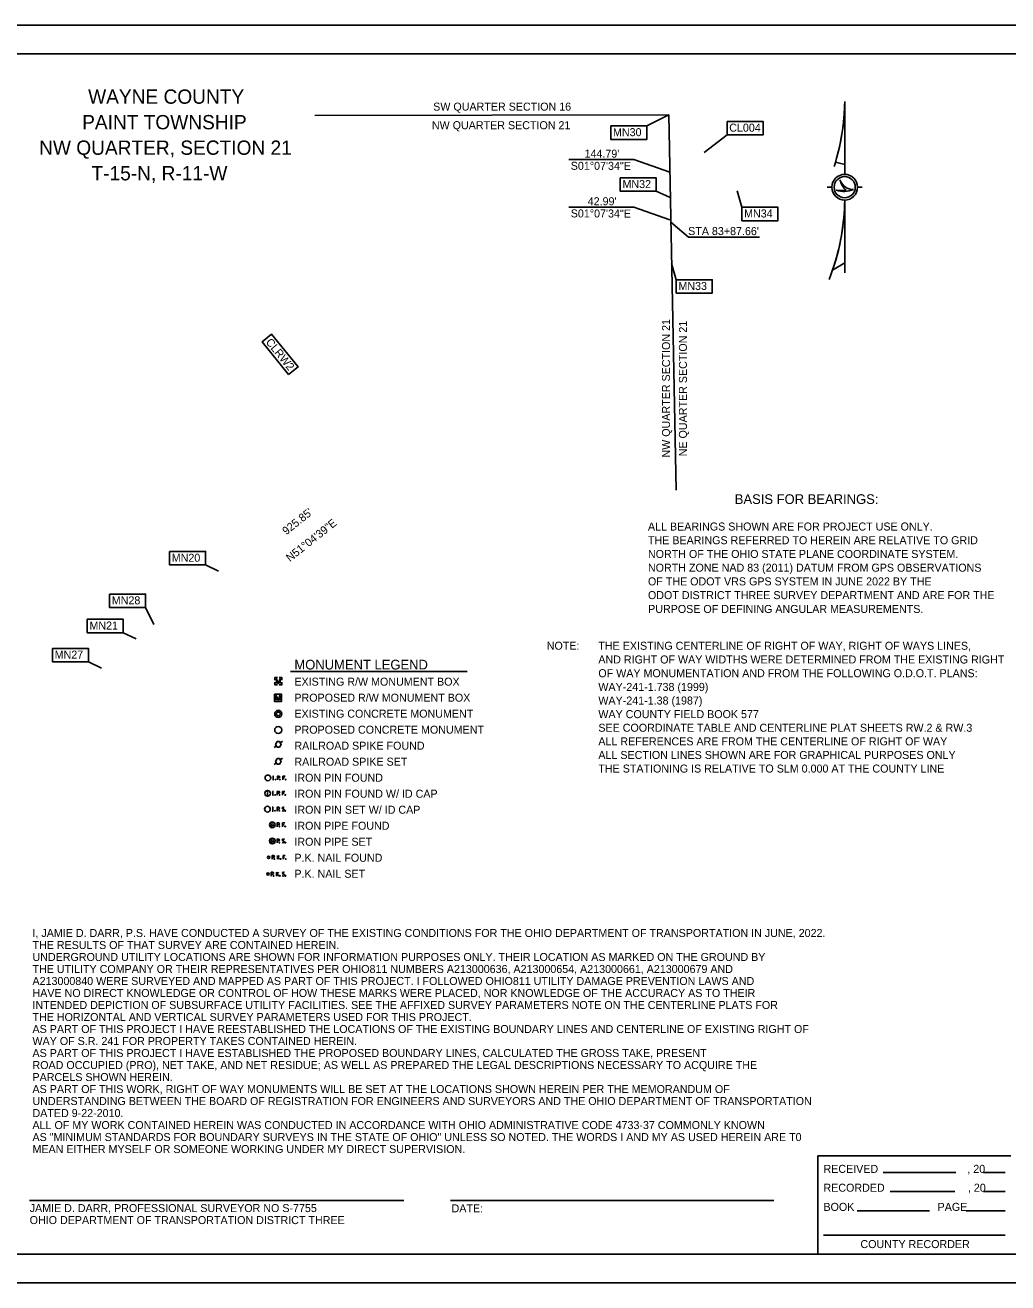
# Model space of a CAD drawing. Extents: x 2183298 to 2188248, y 369076 to 371276.
# Drawn here: x 2184773 to 2186493, y 369076 to 371276 of the extents above; entities that cross this region are included whole.
import ezdxf

# ---------------------------------------------------------------- set-up
doc = ezdxf.new("R2010")
doc.units = 0
for name, color, linetype in [('_CIVIL_CONSTRUCTION', 7, 'Continuous'), ('Default', 7, 'Continuous'), ('RD_X_RR_Cells', 7, 'Continuous'), ('SC_Scratch1', 7, 'Continuous'), ('SV_P_Mon_Cells_Set', 7, 'Continuous'), ('SV_X_Mon_Cells_Found', 7, 'Continuous'), ('SV_X_Shot_Marker', 7, 'Continuous')]:
    doc.layers.add(name, color=color, linetype=linetype)

msp = doc.modelspace()

# ---------------------------------------------------------------- linework, layer by layer
at = {"layer": 'RD_X_RR_Cells'}
msp.add_lwpolyline([(2183447.7, 371226.3), (2186647.7, 371226.3), (2186647.7, 369126.3), (2183447.7, 369126.3)], close=True, dxfattribs=at)
at = {"layer": 'SC_Scratch1'}
for q in [(2185280, 371118.1), (2185912.2, 370462.7)]:
    msp.add_line((2185899.3, 371119.5), q, dxfattribs=at)
at = {"layer": 'SV_P_Mon_Cells_Set'}
for p, q in [((2186207.2, 371015.3), (2186207.2, 371142.8)), ((2186191.3, 371036.9), (2186207.2, 371032.5)), ((2186176.7, 370992.8), (2186184.7, 370992.8)), ((2186229.7, 370992.8), (2186237.7, 370992.8)), ((2186207.2, 370842.8), (2186207.2, 370970.3)), ((2186207.2, 370860.3), (2186185.8, 370847.5))]:
    msp.add_line(p, q, dxfattribs=at)
for points in [[(2186191.2, 371036.9), (2186191.3, 371036.9), (2186207.2, 371032.5), (2186207.2, 371142.8)], [(2186185.8, 370847.5), (2186207.2, 370860.3), (2186207.2, 370970.3)]]:
    msp.add_lwpolyline(points, dxfattribs=at)
for radius in [22.5, 18.5]:
    msp.add_circle((2186207.2, 370992.8), radius, dxfattribs=at)
for centre, radius, start, end in [((2185813, 371148.4), 394.3, 342.4153, 359.1947), ((2185813, 371148.4), 394.3, 343.5754, 359.1947), ((2186206.1, 371030.7), 45.2, 252.4874, 291.486), ((2186201.7, 371044), 57.1, 260.7277, 277.8734), ((2186223, 371014.1), 25.5, 199.1575, 269.3709), ((2186233.8, 371013.7), 35.8, 192.8556, 227.3141), ((2185813, 370975.9), 394.3, 338.5054, 359.1947), ((2185813, 370975.9), 394.3, 340.9936, 359.1947)]:
    msp.add_arc(centre, radius, start, end, dxfattribs=at)
at = {"layer": 'SV_X_Mon_Cells_Found'}
msp.add_lwpolyline([(2183297.7, 369076.3), (2186697.7, 369076.3), (2186697.7, 371276.3), (2183297.7, 371276.3)], close=True, dxfattribs=at)
at = {"layer": 'SV_X_Shot_Marker'}
for p, q in [((2185860.9, 371100), (2185899.3, 371119.5)), ((2186001.3, 371084.4), (2185961, 371053.3)), ((2185837.9, 371041.2), (2185724.4, 371041.2)), ((2185837.9, 371041.2), (2185901.3, 371018.9)), ((2186027.3, 370957.7), (2186019.2, 370986.3)), ((2185877.5, 370985.8), (2185902, 370974.7)), ((2185837.9, 370957.9), (2185724.4, 370957.9)), ((2185837.9, 370957.9), (2185901.3, 370935.7)), ((2185934, 370905.2), (2185903, 370931.8)), ((2186058.3, 370905.2), (2185934, 370905.2)), ((2185912.4, 370830.9), (2185904.3, 370859.5)), ((2185088.8, 370332.1), (2185111.3, 370321.2)), ((2184983.9, 370257.6), (2184998.1, 370227.7)), ((2184944.8, 370213.6), (2184967.3, 370202.6)), ((2184883.8, 370162.6), (2184906.4, 370151.7)), ((2185216, 370128.8), (2185216, 370128.8)), ((2185237.2, 370145.4), (2185546.5, 370145.4)), ((2185215.6, 370099.7), (2185215.6, 370099.7)), ((2185223.4, 370023.6), (2185219.4, 370020.6)), ((2185212.7, 370015.6), (2185208.7, 370012.6)), ((2185212.7, 369985.9), (2185208.7, 369982.9)), ((2185223.4, 369993.9), (2185219.4, 369990.9)), ((2185206.2, 369962.8), (2185207.9, 369962.8)), ((2185206.2, 369962.8), (2185207.9, 369962.8)), ((2185206.2, 369956.2), (2185207.9, 369956.2)), ((2185207, 369956.2), (2185207, 369962.8)), ((2185214.7, 369959.7), (2185217.4, 369959.7)), ((2185224.1, 369956.2), (2185224.1, 369962.8)), ((2185224.1, 369962.8), (2185227.9, 369962.8)), ((2185224.1, 369959.6), (2185226.8, 369959.6)), ((2185197.4, 369933.1), (2185197.4, 369929.4)), ((2185205.8, 369935.9), (2185207.4, 369935.9)), ((2185205.8, 369935.9), (2185207.4, 369935.9)), ((2185206.6, 369929.3), (2185206.6, 369935.9)), ((2185214.3, 369932.7), (2185216.9, 369932.7)), ((2185223.6, 369929.3), (2185223.6, 369935.9)), ((2185223.6, 369935.9), (2185227.5, 369935.9)), ((2185223.6, 369932.7), (2185226.4, 369932.7)), ((2185205.3, 369908.3), (2185207, 369908.3)), ((2185205.3, 369908.3), (2185207, 369908.3)), ((2185205.8, 369929.3), (2185207.4, 369929.3)), ((2185206.2, 369901.6), (2185206.2, 369908.3)), ((2185205.3, 369901.6), (2185207, 369901.6)), ((2185213.8, 369905.1), (2185216.5, 369905.1)), ((2185223.3, 369905.9), (2185226.3, 369904.3)), ((2185214, 369877.5), (2185216.6, 369877.5)), ((2185223.3, 369874), (2185223.3, 369880.7)), ((2185223.3, 369880.7), (2185227.2, 369880.7)), ((2185223.3, 369877.5), (2185226.1, 369877.5)), ((2185214, 369849.4), (2185216.6, 369849.4)), ((2185223.4, 369850.2), (2185226.5, 369848.6)), ((2185205.1, 369820.7), (2185207.8, 369820.7)), ((2185214.5, 369817.2), (2185214.5, 369823.8)), ((2185214.5, 369819.6), (2185217.7, 369823.8)), ((2185215.5, 369821), (2185218.3, 369817.2)), ((2185224.3, 369817.2), (2185224.3, 369823.8)), ((2185224.3, 369823.8), (2185228.2, 369823.8)), ((2185224.3, 369820.6), (2185227.1, 369820.6)), ((2185203.7, 369791.4), (2185206.4, 369791.4)), ((2185213, 369787.9), (2185213, 369794.6)), ((2185213, 369790.3), (2185216.2, 369794.6)), ((2185214, 369791.7), (2185216.8, 369787.9)), ((2185223.6, 369792.2), (2185226.6, 369790.6)), ((2186160, 369126.3), (2186160, 369298.7)), ((2186160, 369298.7), (2186497.7, 369298.7)), ((2186274.3, 369269.2), (2186401.6, 369269.2)), ((2186449.9, 369269.2), (2186487.7, 369269.2)), ((2186286.8, 369235.9), (2186399.9, 369235.9)), ((2186449.9, 369235.9), (2186487.7, 369235.9)), ((2184780.5, 369220.5), (2185435.7, 369220.5)), ((2185517.5, 369220.5), (2186083.4, 369220.5)), ((2186229, 369202.5), (2186355.6, 369202.5)), ((2186419.6, 369202.5), (2186487.7, 369202.5)), ((2186170, 369159.7), (2186487.7, 369159.7))]:
    msp.add_line(p, q, dxfattribs=at)
for points in [[(2185797.9, 371100), (2185860.9, 371100), (2185860.9, 371076.5), (2185797.9, 371076.5)], [(2186001.3, 371107.8), (2186064.3, 371107.8), (2186064.3, 371084.4), (2186001.3, 371084.4)], [(2185814.5, 371009.2), (2185877.5, 371009.2), (2185877.5, 370985.8), (2185814.5, 370985.8)], [(2186027.3, 370957.7), (2186090.3, 370957.7), (2186090.3, 370934.3), (2186027.3, 370934.3)], [(2185912.4, 370830.9), (2185975.4, 370830.9), (2185975.4, 370807.5), (2185912.4, 370807.5)], [(2185234.1, 370665.3), (2185250.6, 370678.6), (2185204.4, 370735.7), (2185187.9, 370722.4)], [(2185025.8, 370355.6), (2185088.8, 370355.6), (2185088.8, 370332.1), (2185025.8, 370332.1)], [(2184920.9, 370281.1), (2184983.9, 370281.1), (2184983.9, 370257.6), (2184920.9, 370257.6)], [(2184881.8, 370237), (2184944.8, 370237), (2184944.8, 370213.6), (2184881.8, 370213.6)], [(2184820.8, 370186), (2184883.8, 370186), (2184883.8, 370162.6), (2184820.8, 370162.6)], [(2185214.2, 370023.1), (2185217.9, 370023.1), (2185220.9, 370018.1), (2185217.9, 370013.1), (2185214.2, 370013.1), (2185211.2, 370018.1)], [(2185214.2, 369993.4), (2185217.9, 369993.4), (2185220.9, 369988.4), (2185217.9, 369983.4), (2185214.2, 369983.4), (2185211.2, 369988.4)]]:
    msp.add_lwpolyline(points, close=True, dxfattribs=at)
for points in [[(2185209.8, 370130.4), (2185209.8, 370135.1), (2185214.5, 370135.1)], [(2185213, 370124.6), (2185213, 370133), (2185216, 370124.6), (2185219.1, 370133), (2185219.1, 370124.6)], [(2185217.5, 370135.1), (2185222.3, 370135.1), (2185222.3, 370130.4)], [(2185209.3, 370106), (2185221.8, 370106), (2185221.8, 370093.5), (2185209.3, 370093.5), (2185209.3, 370106)], [(2185214.5, 370122.5), (2185209.8, 370122.5), (2185209.8, 370127.2)], [(2185222.3, 370127.2), (2185222.3, 370122.5), (2185217.5, 370122.5)], [(2185212.5, 370095.6), (2185212.5, 370103.9), (2185215.6, 370095.6), (2185218.7, 370103.9), (2185218.7, 370095.6)], [(2185217.4, 369962.8), (2185214.7, 369962.8), (2185214.7, 369956.2)], [(2185216.9, 369935.9), (2185214.3, 369935.9), (2185214.3, 369929.3)], [(2185216.5, 369908.3), (2185213.8, 369908.3), (2185213.8, 369901.6)], [(2185216.6, 369880.7), (2185214, 369880.7), (2185214, 369874)], [(2185216.6, 369852.6), (2185214, 369852.6), (2185214, 369845.9)], [(2185207.8, 369823.8), (2185205.1, 369823.8), (2185205.1, 369817.2)], [(2185206.4, 369794.6), (2185203.7, 369794.6), (2185203.7, 369787.9)]]:
    msp.add_lwpolyline(points, dxfattribs=at)
for centre, radius in [((2185216, 370071.5), 6.25), ((2185216, 370071.5), 3.33), ((2185216, 370043.4), 6.25), ((2185197.9, 369959.5), 5), ((2185211, 369956.6), 0.583), ((2185218.7, 369956.6), 0.583), ((2185228.9, 369956.6), 0.583), ((2185197.4, 369932.6), 5), ((2185197.4, 369935.3), 0.667), ((2185210.6, 369929.7), 0.583), ((2185218.3, 369929.7), 0.583), ((2185228.4, 369929.7), 0.583), ((2185197, 369904.9), 5), ((2185210.2, 369902.1), 0.583), ((2185217.9, 369902.1), 0.583), ((2185228.5, 369902), 0.583), ((2185205.6, 369877.4), 5), ((2185205.6, 369877.4), 2.06), ((2185218, 369874.5), 0.583), ((2185228.1, 369874.5), 0.583), ((2185205.6, 369849.2), 5), ((2185205.6, 369849.2), 2.08), ((2185218, 369846.3), 0.583), ((2185228.7, 369846.3), 0.583), ((2185199.2, 369820.5), 2.07), ((2185209.2, 369817.6), 0.583), ((2185220.1, 369817.6), 0.583), ((2185229.1, 369817.6), 0.583), ((2185197.9, 369791.2), 2.06), ((2185207.7, 369788.3), 0.583), ((2185218.8, 369788.3), 0.583), ((2185228.8, 369788.3), 0.583)]:
    msp.add_circle(centre, radius, dxfattribs=at)
for centre, radius, start, end in [((2185217.1, 369961.2), 1.62, 278.8803, 81.1197), ((2185216.7, 369934.3), 1.62, 278.8803, 81.1197), ((2185216.3, 369906.7), 1.62, 278.8803, 81.1197), ((2185224.9, 369904.8), 3.49, 61.3463, 118.6537), ((2185223.9, 369906.9), 1.18, 126.2587, 236.3675), ((2185224.8, 369904.4), 2.76, 223.6695, 304.3963), ((2185225.3, 369903.2), 1.48, 311.4883, 47.9358), ((2185216.4, 369879.1), 1.62, 278.8803, 81.1197), ((2185216.4, 369851), 1.62, 278.8803, 81.1197), ((2185224, 369851.2), 1.18, 126.2587, 236.3675), ((2185224.9, 369848.7), 2.76, 223.6695, 304.3963), ((2185225, 369849.1), 3.49, 61.3463, 118.6537), ((2185225.5, 369847.5), 1.48, 311.4883, 47.9358), ((2185207.6, 369822.2), 1.62, 278.8803, 81.1197), ((2185206.1, 369793), 1.62, 278.8803, 81.1197), ((2185224.2, 369793.2), 1.18, 126.2587, 236.3675), ((2185225.1, 369790.7), 2.76, 223.6695, 304.3963), ((2185225.2, 369791.1), 3.49, 61.3463, 118.6537), ((2185225.6, 369789.5), 1.48, 311.4883, 47.9358)]:
    msp.add_arc(centre, radius, start, end, dxfattribs=at)

# ---------------------------------------------------------------- texts
at = {"layer": '_CIVIL_CONSTRUCTION'}
for s, rotation, p in [("144.79'", 359.8857, (2185751.9, 371044.6)), ('S01°07\'34"E', 359.8857, (2185727.8, 371023.3)), ("42.99'", 359.8857, (2185757.5, 370961.3)), ('S01°07\'34"E', 359.8857, (2185727.8, 370940)), ("STA 83+87.66'", 359.8857, (2185933.2, 370909.2)), ("925.85'", 38.4323, (2185229.9, 370383.9)), ('N51°04\'39"E', 38.4323, (2185236.4, 370336.9))]:
    msp.add_text(s, height=14, rotation=rotation, dxfattribs=at).set_placement(p)
at = {"layer": 'Default'}
for s, p in [('I, JAMIE D. DARR, P.S. HAVE CONDUCTED A SURVEY OF THE EXISTING CONDITIONS FOR THE OHIO DEPARTMENT OF TRANSPORTATION IN JUNE, 2022.', (2184785.9, 369681.3)), ('THE RESULTS OF THAT SURVEY ARE CONTAINED HEREIN.', (2184785.9, 369660.3)), ('UNDERGROUND UTILITY LOCATIONS ARE SHOWN FOR INFORMATION PURPOSES ONLY. THEIR LOCATION AS MARKED ON THE GROUND BY', (2184785.9, 369639.3)), ('THE UTILITY COMPANY OR THEIR REPRESENTATIVES PER OHIO811 NUMBERS A213000636, A213000654, A213000661, A213000679 AND', (2184785.9, 369618.3)), ('A213000840 WERE SURVEYED AND MAPPED AS PART OF THIS PROJECT. I FOLLOWED OHIO811 UTILITY DAMAGE PREVENTION LAWS AND', (2184785.9, 369597.3)), ('HAVE NO DIRECT KNOWLEDGE OR CONTROL OF HOW THESE MARKS WERE PLACED, NOR KNOWLEDGE OF THE ACCURACY AS TO THEIR', (2184785.9, 369576.3)), ('INTENDED DEPICTION OF SUBSURFACE UTILITY FACILITIES. SEE THE AFFIXED SURVEY PARAMETERS NOTE ON THE CENTERLINE PLATS FOR', (2184785.9, 369555.3)), ('THE HORIZONTAL AND VERTICAL SURVEY PARAMETERS USED FOR THIS PROJECT.', (2184785.9, 369534.3)), ('AS PART OF THIS PROJECT I HAVE REESTABLISHED THE LOCATIONS OF THE EXISTING BOUNDARY LINES AND CENTERLINE OF EXISTING RIGHT OF', (2184785.9, 369513.3)), ('WAY OF S.R. 241 FOR PROPERTY TAKES CONTAINED HEREIN.', (2184785.9, 369492.3)), ('AS PART OF THIS PROJECT I HAVE ESTABLISHED THE PROPOSED BOUNDARY LINES, CALCULATED THE GROSS TAKE, PRESENT', (2184785.9, 369471.3)), ('ROAD OCCUPIED (PRO), NET TAKE, AND NET RESIDUE; AS WELL AS PREPARED THE LEGAL DESCRIPTIONS NECESSARY TO ACQUIRE THE', (2184785.9, 369450.3)), ('PARCELS SHOWN HEREIN.', (2184785.9, 369429.3)), ('AS PART OF THIS WORK, RIGHT OF WAY MONUMENTS WILL BE SET AT THE LOCATIONS SHOWN HEREIN PER THE MEMORANDUM OF', (2184785.9, 369408.3)), ('UNDERSTANDING BETWEEN THE BOARD OF REGISTRATION FOR ENGINEERS AND SURVEYORS AND THE OHIO DEPARTMENT OF TRANSPORTATION', (2184785.9, 369387.3)), ('DATED 9-22-2010.', (2184785.9, 369366.3)), ('ALL OF MY WORK CONTAINED HEREIN WAS CONDUCTED IN ACCORDANCE WITH OHIO ADMINISTRATIVE CODE 4733-37 COMMONLY KNOWN', (2184785.9, 369345.3)), ('AS "MINIMUM STANDARDS FOR BOUNDARY SURVEYS IN THE STATE OF OHIO" UNLESS SO NOTED. THE WORDS I AND MY AS USED HEREIN ARE T0', (2184785.9, 369324.3)), ('MEAN EITHER MYSELF OR SOMEONE WORKING UNDER MY DIRECT SUPERVISION. ', (2184785.9, 369303.3))]:
    msp.add_text(s, height=14, dxfattribs=at).set_placement(p)
at = {"layer": 'SC_Scratch1'}
for s, p in [('SW QUARTER SECTION 16', (2185487.1, 371126.8)), ('NW QUARTER SECTION 21', (2185484.8, 371094.3))]:
    msp.add_text(s, height=14, dxfattribs=at).set_placement(p)
for s, p in [('NW QUARTER SECTION 21', (2185901.5, 370519.9)), ('NE QUARTER SECTION 21', (2185931.1, 370522.1))]:
    msp.add_text(s, height=14, rotation=90, dxfattribs=at).set_placement(p)
at = {"layer": 'SV_P_Mon_Cells_Set'}
for s, p in [('               WAYNE COUNTY               ', (2184744, 371138.8)), ('              PAINT TOWNSHIP              ', (2184742.8, 371094.1)), ('          NW QUARTER, SECTION 21          ', (2184704.7, 371049.5)), ('              T-15-N, R-11-W              ', (2184759.2, 371004.8))]:
    msp.add_text(s, height=25, dxfattribs=at).set_placement(p)
at = {"layer": 'SV_X_Shot_Marker'}
for s, height, p in [('MN30', 14, (2185801.7, 371082.1)), ('CL004', 14, (2186005.1, 371090)), ('MN32', 14, (2185818.3, 370991.3)), ('MN34', 14, (2186031.1, 370939.9)), ('MN33', 14, (2185916.2, 370813.1)), ('BASIS FOR BEARINGS:', 17, (2186014.8, 370438.7)), ('ALL BEARINGS SHOWN ARE FOR PROJECT USE ONLY.', 14, (2185862.9, 370392.3)), ('THE BEARINGS REFERRED TO HEREIN ARE RELATIVE TO GRID ', 14, (2185862.9, 370368.3)), ('MN20', 14, (2185029.6, 370337.7)), ('NORTH OF THE OHIO STATE PLANE COORDINATE SYSTEM.     ', 14, (2185862.9, 370344.3)), ('NORTH ZONE NAD 83 (2011) DATUM FROM GPS OBSERVATIONS ', 14, (2185862.9, 370320.3)), ('OF THE ODOT VRS GPS SYSTEM IN JUNE 2022 BY THE       ', 14, (2185862.9, 370296.3)), ('ODOT DISTRICT THREE SURVEY DEPARTMENT AND ARE FOR THE', 14, (2185862.9, 370272.3)), ('MN28', 14, (2184924.7, 370263.2)), ('PURPOSE OF DEFINING ANGULAR MEASUREMENTS.', 14, (2185863.2, 370248.1)), ('MN21', 14, (2184885.6, 370219.1)), ('NOTE:', 14, (2185685.8, 370183.8)), ('THE EXISTING CENTERLINE OF RIGHT OF WAY, RIGHT OF WAYS LINES,', 14, (2185776.1, 370183.7)), ('MN27', 14, (2184824.7, 370168.2)), ('AND RIGHT OF WAY WIDTHS WERE DETERMINED FROM THE EXISTING RIGHT', 14, (2185776.1, 370159.7)), ('MONUMENT LEGEND', 17, (2185244.2, 370149.2)), ('EXISTING R/W MONUMENT BOX', 14, (2185244.2, 370120.9)), ('OF WAY MONUMENTATION AND FROM THE FOLLOWING O.D.O.T. PLANS:', 14, (2185776.1, 370135.7)), ('PROPOSED R/W MONUMENT BOX', 14, (2185244.2, 370092.9)), ('WAY-241-1.738 (1999)', 14, (2185776.1, 370111.7)), ('WAY-241-1.38 (1987)', 14, (2185776.1, 370087.9)), ('EXISTING CONCRETE MONUMENT', 14, (2185244.2, 370064.9)), ('WAY COUNTY FIELD BOOK 577', 14, (2185776.1, 370064.1)), ('PROPOSED CONCRETE MONUMENT', 14, (2185244.2, 370036.9)), ('SEE COORDINATE TABLE AND CENTERLINE PLAT SHEETS RW.2 & RW.3', 14, (2185776.1, 370040.3)), ('RAILROAD SPIKE FOUND', 14, (2185244.2, 370008.9)), ('ALL REFERENCES ARE FROM THE CENTERLINE OF RIGHT OF WAY', 14, (2185776.1, 370016.5)), ('ALL SECTION LINES SHOWN ARE FOR GRAPHICAL PURPOSES ONLY', 14, (2185776.1, 369992.7)), ('RAILROAD SPIKE SET', 14, (2185244.2, 369980.9)), ('THE STATIONING IS RELATIVE TO SLM 0.000 AT THE COUNTY LINE', 14, (2185776.1, 369968.9)), ('IRON PIN FOUND', 14, (2185244.2, 369952.9)), ('IRON PIN FOUND W/ ID CAP', 14, (2185244.2, 369924.9)), ('IRON PIN SET W/ ID CAP', 14, (2185244.2, 369896.9)), ('IRON PIPE FOUND', 14, (2185244.2, 369868.9)), ('IRON PIPE SET', 14, (2185244.2, 369840.9)), ('P.K. NAIL FOUND', 14, (2185244.2, 369812.9)), ('P.K. NAIL SET', 14, (2185244.2, 369784.9)), ('RECEIVED                              , 20', 14, (2186170, 369268.7)), ('RECORDED                            , 20', 14, (2186170, 369235.7)), ('JAMIE D. DARR, PROFESSIONAL SURVEYOR NO S-7755', 14, (2184781, 369200.1)), ('DATE:', 14, (2185519.3, 369199.6)), ('BOOK                            PAGE', 14, (2186170, 369202.2)), ('OHIO DEPARTMENT OF TRANSPORTATION DISTRICT THREE', 14, (2184781, 369179.1)), ('COUNTY RECORDER', 14, (2186234.7, 369137.1))]:
    msp.add_text(s, height=height, dxfattribs=at).set_placement(p)
msp.add_text('CLRW2', height=14, rotation=309.2042, dxfattribs=at).set_placement((2185193.2, 370721.5))

doc.saveas('drawing.dxf')
